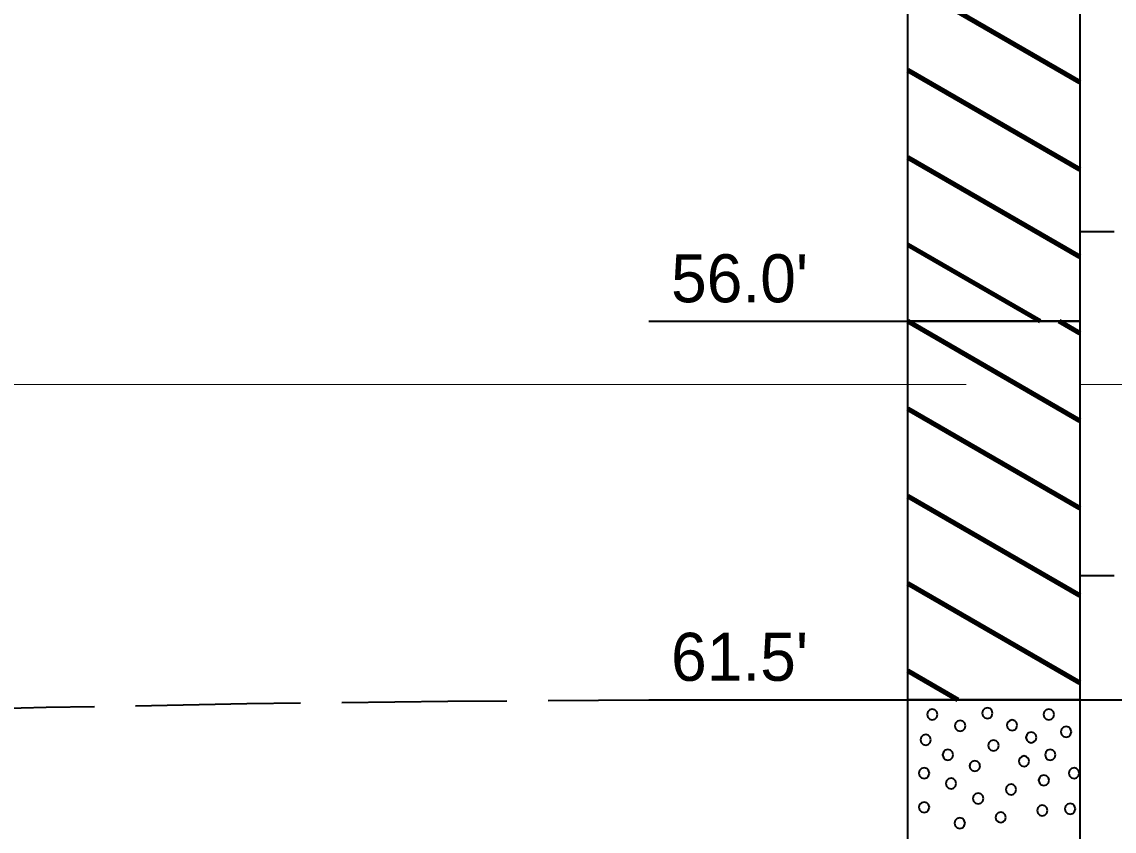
# Model space of a CAD drawing. Extents: x -582 to 653, y -817 to -3.
# Drawn here: x 14.65 to 30.53, y -550.62 to -538.86 of the extents above; entities that cross this region are included whole.
import ezdxf

# ---------------------------------------------------------------- set-up
doc = ezdxf.new("R2010")
doc.units = 0
doc.header["$LTSCALE"] = 0.4
doc.linetypes.add('LONG_DASHED', pattern=[7.5, 6, -1.5])
for name, color, linetype, lineweight in [('26', 7, 'LONG_DASHED', 40), ('27', 7, 'Continuous', 40), ('7', 7, 'Continuous', 13)]:
    doc.layers.add(name, color=color, linetype=linetype, lineweight=lineweight)

msp = doc.modelspace()

# ---------------------------------------------------------------- linework, layer by layer
at = {"layer": '26'}
msp.add_spline([(-40.6865, -549.8893), (-29.2387, -549.7528), (-25.4713, -549.7528), (-22.9713, -549.7528), (23.7613, -548.7128), (27.5287, -548.7128), (30.0287, -548.7128), (46.0791, -548.7128)], degree=3, dxfattribs=at)
at = {"layer": '27', "lineweight": 158}
for p, q in [((27.5287, -538.2929), (30.0287, -539.7363)), ((27.5287, -539.5629), (30.0287, -541.0063)), ((27.5287, -540.8329), (30.0287, -542.2763)), ((27.5287, -542.1029), (29.4509, -543.2128)), ((27.5287, -543.2128), (30.0287, -544.6562)), ((29.7282, -543.2128), (30.0287, -543.3862)), ((27.5287, -544.4828), (30.0287, -545.9262)), ((27.5287, -545.7528), (30.0287, -547.1963)), ((27.5287, -547.0229), (30.0287, -548.4663)), ((27.5287, -548.2929), (28.256, -548.7128))]:
    msp.add_line(p, q, dxfattribs=at)
at = {"layer": '27'}
for p, q in [((30.5287, -541.9128), (30.0287, -541.9128)), ((23.7613, -543.2128), (27.5287, -543.2128)), ((30.5287, -546.9128), (30.0287, -546.9128)), ((23.7613, -548.7128), (27.5287, -548.7128))]:
    msp.add_line(p, q, dxfattribs=at)
for points in [[(27.5287, -533.2128), (30.0287, -533.2128), (30.0287, -543.2128), (27.5287, -543.2128)], [(27.5287, -543.2128), (30.0287, -543.2128), (30.0287, -548.7128), (27.5287, -548.7128)], [(27.5287, -548.7128), (30.0287, -548.7128), (30.0287, -556.4128), (27.5287, -556.4128)], [(27.9606, -548.9255), (27.9504, -548.8874), (27.9225, -548.8595), (27.8844, -548.8493), (27.8463, -548.8595), (27.8184, -548.8874), (27.8082, -548.9255), (27.8184, -548.9636), (27.8463, -548.9914), (27.8844, -549.0017), (27.9225, -548.9914), (27.9504, -548.9636)], [(28.7616, -548.9059), (28.7513, -548.8678), (28.7235, -548.8399), (28.6854, -548.8297), (28.6473, -548.8399), (28.6194, -548.8678), (28.6092, -548.9059), (28.6194, -548.944), (28.6473, -548.9719), (28.6854, -548.9821), (28.7235, -548.9719), (28.7513, -548.944)], [(29.6552, -548.9255), (29.645, -548.8874), (29.6171, -548.8595), (29.579, -548.8493), (29.5409, -548.8595), (29.513, -548.8874), (29.5028, -548.9255), (29.513, -548.9636), (29.5409, -548.9915), (29.579, -549.0017), (29.6171, -548.9915), (29.645, -548.9636)], [(28.3655, -549.0907), (28.3553, -549.0526), (28.3274, -549.0247), (28.2893, -549.0145), (28.2512, -549.0247), (28.2233, -549.0526), (28.2131, -549.0907), (28.2233, -549.1288), (28.2512, -549.1567), (28.2893, -549.1669), (28.3274, -549.1567), (28.3553, -549.1288)], [(29.1206, -549.0817), (29.1104, -549.0436), (29.0825, -549.0157), (29.0444, -549.0055), (29.0063, -549.0157), (28.9784, -549.0436), (28.9682, -549.0817), (28.9784, -549.1198), (29.0063, -549.1477), (29.0444, -549.1579), (29.0825, -549.1477), (29.1104, -549.1198)], [(27.8644, -549.2933), (27.8542, -549.2552), (27.8263, -549.2273), (27.7882, -549.2171), (27.7501, -549.2273), (27.7222, -549.2552), (27.712, -549.2933), (27.7222, -549.3314), (27.7501, -549.3593), (27.7882, -549.3695), (27.8263, -549.3593), (27.8542, -549.3314)], [(29.3988, -549.259), (29.3886, -549.2209), (29.3607, -549.193), (29.3226, -549.1828), (29.2845, -549.193), (29.2566, -549.2209), (29.2464, -549.259), (29.2566, -549.2971), (29.2845, -549.325), (29.3226, -549.3352), (29.3607, -549.325), (29.3886, -549.2971)], [(29.9061, -549.1776), (29.8959, -549.1395), (29.868, -549.1116), (29.8299, -549.1014), (29.7918, -549.1116), (29.7639, -549.1395), (29.7537, -549.1776), (29.7639, -549.2157), (29.7918, -549.2436), (29.8299, -549.2538), (29.868, -549.2436), (29.8959, -549.2157)], [(28.8505, -549.3765), (28.8403, -549.3384), (28.8124, -549.3105), (28.7743, -549.3003), (28.7362, -549.3105), (28.7083, -549.3384), (28.6981, -549.3765), (28.7083, -549.4146), (28.7362, -549.4425), (28.7743, -549.4527), (28.8124, -549.4425), (28.8403, -549.4146)], [(28.1873, -549.512), (28.1771, -549.4739), (28.1492, -549.446), (28.1111, -549.4358), (28.073, -549.446), (28.0451, -549.4739), (28.0349, -549.512), (28.0451, -549.5501), (28.073, -549.578), (28.1111, -549.5882), (28.1492, -549.578), (28.1771, -549.5501)], [(29.2946, -549.6048), (29.2844, -549.5667), (29.2565, -549.5388), (29.2184, -549.5286), (29.1803, -549.5388), (29.1524, -549.5667), (29.1422, -549.6048), (29.1524, -549.6429), (29.1803, -549.6708), (29.2184, -549.681), (29.2565, -549.6708), (29.2844, -549.6429)], [(29.676, -549.512), (29.6658, -549.4739), (29.6379, -549.446), (29.5998, -549.4358), (29.5617, -549.446), (29.5338, -549.4739), (29.5236, -549.512), (29.5338, -549.5501), (29.5617, -549.578), (29.5998, -549.5882), (29.6379, -549.578), (29.6658, -549.5501)], [(27.8415, -549.7777), (27.8313, -549.7396), (27.8034, -549.7117), (27.7653, -549.7015), (27.7272, -549.7117), (27.6993, -549.7396), (27.6891, -549.7777), (27.6993, -549.8158), (27.7272, -549.8437), (27.7653, -549.8539), (27.8034, -549.8437), (27.8313, -549.8158)], [(28.5789, -549.6734), (28.5686, -549.6353), (28.5408, -549.6074), (28.5027, -549.5972), (28.4646, -549.6074), (28.4367, -549.6353), (28.4265, -549.6734), (28.4367, -549.7115), (28.4646, -549.7394), (28.5027, -549.7496), (28.5408, -549.7394), (28.5686, -549.7115)], [(30.0217, -549.7777), (30.0115, -549.7396), (29.9836, -549.7117), (29.9455, -549.7015), (29.9074, -549.7117), (29.8796, -549.7396), (29.8693, -549.7777), (29.8796, -549.8158), (29.9074, -549.8437), (29.9455, -549.8539), (29.9836, -549.8437), (30.0115, -549.8158)], [(28.2331, -549.9277), (28.2229, -549.8896), (28.195, -549.8617), (28.1569, -549.8515), (28.1188, -549.8617), (28.0909, -549.8896), (28.0807, -549.9277), (28.0909, -549.9658), (28.1188, -549.9937), (28.1569, -550.0039), (28.195, -549.9937), (28.2229, -549.9658)], [(29.5832, -549.8819), (29.5729, -549.8438), (29.5451, -549.8159), (29.507, -549.8057), (29.4689, -549.8159), (29.441, -549.8438), (29.4308, -549.8819), (29.441, -549.92), (29.4689, -549.9479), (29.507, -549.9581), (29.5451, -549.9479), (29.5729, -549.92)], [(29.1052, -550.0154), (29.095, -549.9773), (29.0671, -549.9494), (29.029, -549.9392), (28.9909, -549.9494), (28.963, -549.9773), (28.9528, -550.0154), (28.963, -550.0535), (28.9909, -550.0814), (29.029, -550.0916), (29.0671, -550.0814), (29.095, -550.0535)], [(27.8415, -550.2735), (27.8313, -550.2354), (27.8034, -550.2075), (27.7653, -550.1973), (27.7272, -550.2075), (27.6993, -550.2354), (27.6891, -550.2735), (27.6993, -550.3116), (27.7272, -550.3394), (27.7653, -550.3497), (27.8034, -550.3394), (27.8313, -550.3116)], [(28.6272, -550.1463), (28.617, -550.1082), (28.5891, -550.0803), (28.551, -550.0701), (28.5129, -550.0803), (28.485, -550.1082), (28.4748, -550.1463), (28.485, -550.1844), (28.5129, -550.2123), (28.551, -550.2225), (28.5891, -550.2123), (28.617, -550.1844)], [(28.9551, -550.4209), (28.9449, -550.3828), (28.917, -550.3549), (28.8789, -550.3447), (28.8408, -550.3549), (28.813, -550.3828), (28.8027, -550.4209), (28.813, -550.459), (28.8408, -550.4869), (28.8789, -550.4971), (28.917, -550.4869), (28.9449, -550.459)], [(29.5603, -550.3205), (29.5501, -550.2824), (29.5222, -550.2545), (29.4841, -550.2443), (29.446, -550.2545), (29.4181, -550.2824), (29.4079, -550.3205), (29.4181, -550.3586), (29.446, -550.3865), (29.4841, -550.3967), (29.5222, -550.3865), (29.5501, -550.3586)], [(29.9645, -550.2963), (29.9543, -550.2582), (29.9264, -550.2304), (29.8883, -550.2201), (29.8502, -550.2304), (29.8223, -550.2582), (29.8121, -550.2963), (29.8223, -550.3344), (29.8502, -550.3623), (29.8883, -550.3725), (29.9264, -550.3623), (29.9543, -550.3344)], [(28.3602, -550.5048), (28.35, -550.4667), (28.3221, -550.4388), (28.284, -550.4286), (28.2459, -550.4388), (28.218, -550.4667), (28.2078, -550.5048), (28.218, -550.5429), (28.2459, -550.5708), (28.284, -550.581), (28.3221, -550.5708), (28.35, -550.5429)]]:
    msp.add_lwpolyline(points, close=True, dxfattribs=at)
at = {"layer": '7'}
for p, q in [((-23.9857, -544.1328), (27.5287, -544.1328)), ((-22.9713, -544.1328), (28.379, -544.1328)), ((30.0287, -544.1328), (67.308, -544.1328))]:
    msp.add_line(p, q, dxfattribs=at)

# ---------------------------------------------------------------- texts
at = {"layer": '27'}
for s, p in [("56.0'", (24.0852, -542.9363)), ("61.5'", (24.0852, -548.4363))]:
    msp.add_text(s, height=0.6976, dxfattribs=at).set_placement(p)

doc.saveas('drawing.dxf')
